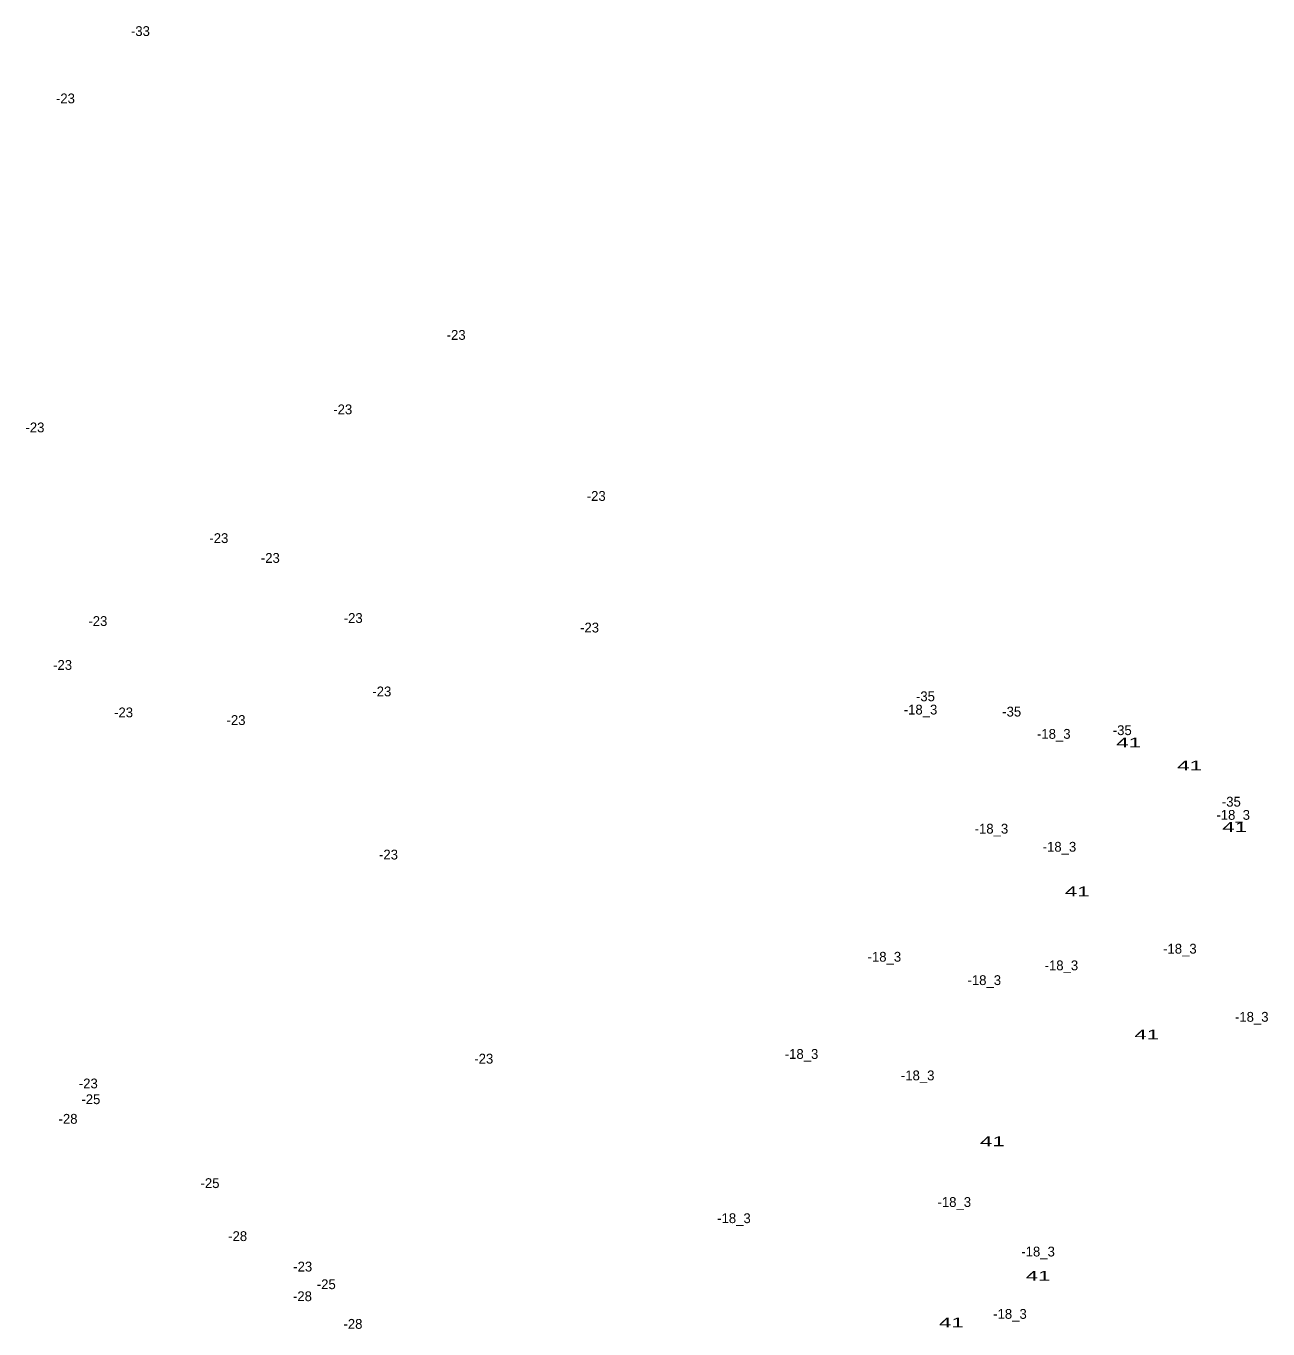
# Model space of a CAD drawing. Extents: x -657046 to -655830, y -1000534 to -999433.
# Drawn here: x -656336 to -655830, y -999977 to -999446 of the extents above; entities that cross this region are included whole.
import ezdxf
from ezdxf.enums import TextEntityAlignment as Align

# ---------------------------------------------------------------- set-up
doc = ezdxf.new("R2010")
doc.units = 0
doc.header["$LTSCALE"] = 1.6
doc.layers.add('24', color=7, linetype='Continuous')

msp = doc.modelspace()

# ---------------------------------------------------------------- texts
at = {"layer": '24'}
for s, p in [('-33', (-656289.705, -999450.23)), ('-23', (-656320.255, -999477.64)), ('-23', (-656161.095, -999573.93)), ('-23', (-656207.285, -999604.25)), ('-23', (-656332.675, -999611.6)), ('-23', (-656104.035, -999639.49)), ('-23', (-656257.755, -999656.67)), ('-23', (-656236.795, -999664.73)), ('-23', (-656203.025, -999689.2)), ('-23', (-656307.045, -999690.44)), ('-23', (-656106.745, -999693.08)), ('-23', (-656321.415, -999708.3)), ('-23', (-656191.375, -999719.1)), ('-35', (-655969.915, -999721.08)), ('-18_3', (-655971.926, -999726.48)), ('-23', (-656296.575, -999727.64)), ('-23', (-656250.765, -999730.75)), ('-35', (-655934.775, -999727.3)), ('-18_3', (-655917.636, -999736.37)), ('-35', (-655889.745, -999734.87)), ('-35', (-655845.305, -999763.99)), ('-18_3', (-655844.556, -999769.35)), ('-18_3', (-655943.036, -999774.97)), ('-18_3', (-655915.326, -999782.34)), ('-23', (-656188.655, -999785.51)), ('-18_3', (-655986.656, -999827.13)), ('-18_3', (-655866.266, -999823.84)), ('-18_3', (-655914.536, -999830.63)), ('-18_3', (-655945.946, -999836.64)), ('-18_3', (-655836.996, -999851.58)), ('-23', (-656149.835, -999868.61)), ('-18_3', (-656020.396, -999866.7)), ('-23', (-656310.945, -999878.71)), ('-18_3', (-655973.086, -999875.43)), ('-25', (-656309.895, -999885.12)), ('-28', (-656319.205, -999893.11)), ('-25', (-656261.365, -999919.29)), ('-18_3', (-655958.166, -999926.98)), ('-18_3', (-656047.926, -999933.57)), ('-28', (-656250.105, -999940.87)), ('-18_3', (-655924.036, -999947.15)), ('-23', (-656223.595, -999953.27)), ('-28', (-656223.705, -999965.34)), ('-25', (-656214.005, -999960.46)), ('-18_3', (-655935.486, -999972.54)), ('-28', (-656203.135, -999976.6))]:
    msp.add_text(s, height=4, dxfattribs=at).set_placement(p, align=Align.CENTER)
at = {"layer": '24', "width": 1.7}
for p in [(-655887.133, -999739.91), (-655862.283, -999749.24), (-655843.943, -999774.29), (-655908.093, -999800.5), (-655879.753, -999858.76), (-655942.643, -999902.26), (-655924.013, -999957.01), (-655959.333, -999976.04)]:
    msp.add_text('41', height=4, dxfattribs=at).set_placement(p, align=Align.CENTER)

doc.saveas('drawing.dxf')
